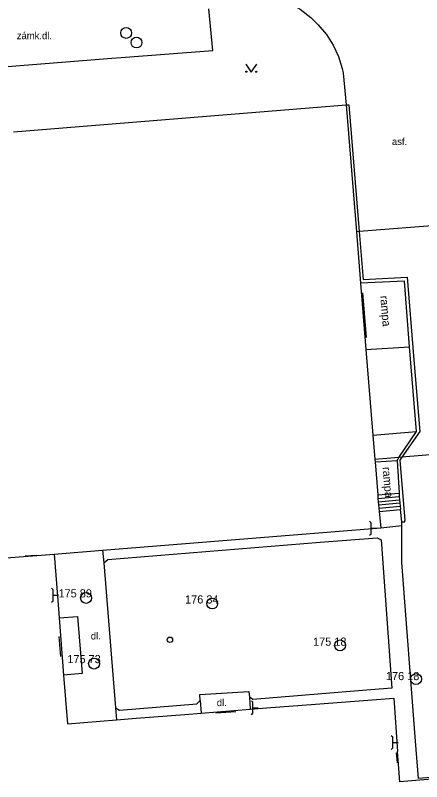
# Model space of a CAD drawing. Extents: x -541281 to -539153, y -1183881 to -1182141.
# Drawn here: x -539516.2 to -539478.9, y -1183295.1 to -1183224.7 of the extents above; entities that cross this region are included whole.
import ezdxf

# ---------------------------------------------------------------- set-up
doc = ezdxf.new("R2010")
doc.units = 0
for name, color, linetype in [('Vrstva 10', 7, 'Continuous'), ('Vrstva 11', 7, 'Continuous'), ('Vrstva 27', 7, 'Continuous'), ('Vrstva 28', 7, 'Continuous'), ('Vrstva 36', 7, 'Continuous'), ('Vrstva 4', 7, 'Continuous'), ('Vrstva 40', 7, 'Continuous'), ('Vrstva 41', 7, 'Continuous'), ('Vrstva 5', 7, 'Continuous'), ('Vrstva 6', 7, 'Continuous')]:
    doc.layers.add(name, color=color, linetype=linetype)

msp = doc.modelspace()

# ---------------------------------------------------------------- linework, layer by layer
at = {"layer": 'Vrstva 10'}
for p, q in [((-539498.11, -1183227.94), (-539498.46, -1183224.11)), ((-539506.51, -1183228.59), (-539498.11, -1183227.94)), ((-539516.96, -1183229.43), (-539507.39, -1183228.66)), ((-539507.39, -1183228.66), (-539506.51, -1183228.59)), ((-539486.15, -1183230.02), (-539485.87, -1183232.95)), ((-539485.87, -1183232.95), (-539485.61, -1183232.94)), ((-539485.61, -1183232.94), (-539484.667, -1183244.582)), ((-539480.51, -1183249.13), (-539484.544, -1183249.32)), ((-539480.05, -1183255.17), (-539480.51, -1183249.13)), ((-539480.27, -1183248.78), (-539479.69, -1183256.01)), ((-539484.05, -1183255.419), (-539480.05, -1183255.17)), ((-539479.39, -1183262.95), (-539480.05, -1183255.17)), ((-539479.69, -1183256.01), (-539479.1, -1183262.96)), ((-539483.412, -1183263.287), (-539479.39, -1183262.95)), ((-539480.94, -1183265.58), (-539480.47, -1183271.14)), ((-539480.74, -1183271.27), (-539480.88, -1183270.12)), ((-539479.5, -1183291.41), (-539480.74, -1183275))]:
    msp.add_line(p, q, dxfattribs=at)
for points in [[(-539492.3, -1183223.07), (-539491.16, -1183223.545), (-539490.09, -1183224.163), (-539489.109, -1183224.914), (-539488.42, -1183225.58)], [(-539488.42, -1183225.58), (-539487.668, -1183226.467), (-539487.045, -1183227.448), (-539486.563, -1183228.506), (-539486.23, -1183229.62), (-539486.15, -1183230.02)], [(-539484.667, -1183244.582), (-539484.31, -1183248.99), (-539480.27, -1183248.78)], [(-539481.19, -1183265.61), (-539481.015, -1183265.352), (-539479.39, -1183262.95)], [(-539479.1, -1183262.96), (-539480.765, -1183265.33), (-539480.94, -1183265.58)], [(-539480.74, -1183275), (-539480.74, -1183271.27), (-539480.46, -1183271.26), (-539480.47, -1183271.14)], [(-539478.08, -1183294.74), (-539479.23, -1183294.84), (-539479.5, -1183291.41)]]:
    msp.add_lwpolyline(points, dxfattribs=at)
at = {"layer": 'Vrstva 11'}
for p, q in [((-539483.212, -1183265.753), (-539481.19, -1183265.61)), ((-539481.19, -1183265.61), (-539481.01, -1183268.61)), ((-539482.966, -1183268.791), (-539481.01, -1183268.61)), ((-539482.941, -1183269.106), (-539480.983, -1183268.924)), ((-539482.916, -1183269.405), (-539480.957, -1183269.223)), ((-539482.892, -1183269.704), (-539480.931, -1183269.523)), ((-539482.868, -1183270.003), (-539480.906, -1183269.821)), ((-539482.844, -1183270.302), (-539480.88, -1183270.12)), ((-539482.67, -1183271.8), (-539480.74, -1183271.602)), ((-539507.73, -1183274.71), (-539488.25, -1183273.13)), ((-539488.25, -1183273.13), (-539483, -1183272.73)), ((-539483, -1183272.73), (-539482.65, -1183272.9)), ((-539482.65, -1183272.9), (-539481.67, -1183286.55)), ((-539508.222, -1183273.869), (-539508.12, -1183275.02)), ((-539508.12, -1183275.02), (-539507.73, -1183274.71)), ((-539508.12, -1183275.02), (-539507.03, -1183288.35)), ((-539512.214, -1183280.081), (-539510.52, -1183279.95)), ((-539510.52, -1183279.95), (-539510.1, -1183285.19)), ((-539510.1, -1183285.19), (-539511.801, -1183285.34)), ((-539481.67, -1183286.55), (-539483.99, -1183286.72)), ((-539494.43, -1183287.58), (-539494.75, -1183287.37)), ((-539494.75, -1183287.37), (-539494.67, -1183288.48)), ((-539483.99, -1183286.72), (-539494.43, -1183287.58)), ((-539506.68, -1183288.56), (-539499.56, -1183287.98)), ((-539499.56, -1183287.98), (-539499.27, -1183287.68)), ((-539499.27, -1183287.68), (-539499.16, -1183288.83)), ((-539507.03, -1183288.35), (-539506.958, -1183289.455)), ((-539507.03, -1183288.35), (-539506.68, -1183288.56))]:
    msp.add_line(p, q, dxfattribs=at)
for points in [[(-539481.01, -1183268.61), (-539480.983, -1183268.924), (-539480.957, -1183269.223), (-539480.931, -1183269.523), (-539480.906, -1183269.821), (-539480.88, -1183270.12)], [(-539499.27, -1183287.68), (-539499.29, -1183287.13), (-539494.81, -1183286.83), (-539494.75, -1183287.37)]]:
    msp.add_lwpolyline(points, dxfattribs=at)
at = {"layer": 'Vrstva 27'}
for p, q in [((-539483.71, -1183271.208), (-539483.568, -1183271.35)), ((-539483.568, -1183272.35), (-539483.568, -1183271.35)), ((-539483.568, -1183271.85), (-539483.08, -1183271.85)), ((-539483.71, -1183272.49), (-539483.568, -1183272.35)), ((-539512.91, -1183277.358), (-539512.768, -1183277.5)), ((-539512.768, -1183278.5), (-539512.768, -1183277.5)), ((-539512.768, -1183278), (-539512.28, -1183278)), ((-539512.91, -1183278.64), (-539512.768, -1183278.5)), ((-539494.56, -1183287.698), (-539494.418, -1183287.84)), ((-539494.418, -1183288.84), (-539494.418, -1183287.84)), ((-539494.418, -1183288.34), (-539493.93, -1183288.34)), ((-539494.56, -1183288.98), (-539494.418, -1183288.84)), ((-539481.72, -1183290.878), (-539481.578, -1183291.02)), ((-539481.578, -1183292.02), (-539481.578, -1183291.02)), ((-539481.578, -1183291.52), (-539481.09, -1183291.52)), ((-539481.72, -1183292.16), (-539481.578, -1183292.02))]:
    msp.add_line(p, q, dxfattribs=at)
for centre in [(-539506.06, -1183226.34), (-539505.11, -1183227.22), (-539509.74, -1183278.25), (-539498.16, -1183278.76), (-539486.42, -1183282.61), (-539509.01, -1183284.28), (-539479.45, -1183285.7)]:
    msp.add_circle(centre, 0.5, dxfattribs=at)
at = {"layer": 'Vrstva 28'}
msp.add_circle((-539502.04, -1183282.09), 0.25, dxfattribs=at)
at = {"layer": 'Vrstva 36'}
msp.add_lwpolyline([(-539495.073, -1183229.201), (-539494.573, -1183229.951), (-539494.073, -1183229.201)], dxfattribs=at)
for centre in [(-539495.023, -1183229.901), (-539494.124, -1183229.901)]:
    msp.add_circle(centre, 0.05, dxfattribs=at)
at = {"layer": 'Vrstva 5'}
for p, q in [((-539516.4, -1183235.41), (-539485.87, -1183232.95)), ((-539534.18, -1183275.9), (-539512.68, -1183274.23)), ((-539512.68, -1183274.23), (-539512.37, -1183278.09)), ((-539493.17, -1183288.36), (-539488.69, -1183288)), ((-539488.69, -1183288), (-539481.48, -1183287.45)), ((-539481.48, -1183287.45), (-539481.14, -1183292.36)), ((-539499.16, -1183288.83), (-539494.67, -1183288.48)), ((-539494.67, -1183288.48), (-539493.17, -1183288.36)), ((-539505.13, -1183289.31), (-539500.66, -1183288.95)), ((-539500.66, -1183288.95), (-539499.16, -1183288.83)), ((-539480.92, -1183295.13), (-539481.06, -1183293.51)), ((-539473.1, -1183294.49), (-539480.92, -1183295.13))]:
    msp.add_line(p, q, dxfattribs=at)
for points in [[(-539485.87, -1183232.95), (-539484.926, -1183244.602), (-539484.544, -1183249.32), (-539484.05, -1183255.419), (-539483.412, -1183263.287), (-539483.229, -1183265.542), (-539483.212, -1183265.753), (-539482.966, -1183268.791), (-539482.941, -1183269.106), (-539482.916, -1183269.405), (-539482.892, -1183269.704), (-539482.868, -1183270.003), (-539482.844, -1183270.302), (-539482.67, -1183271.8)], [(-539476.5, -1183243.96), (-539476.807, -1183243.984), (-539484.667, -1183244.582), (-539484.926, -1183244.602)], [(-539474.83, -1183264.82), (-539475.153, -1183264.848), (-539480.765, -1183265.33), (-539481.015, -1183265.352), (-539483.229, -1183265.542)], [(-539512.68, -1183274.23), (-539508.222, -1183273.869), (-539482.67, -1183271.8)], [(-539512.37, -1183278.09), (-539512.214, -1183280.081), (-539511.801, -1183285.34), (-539511.45, -1183289.81)], [(-539511.45, -1183289.81), (-539506.958, -1183289.455), (-539505.13, -1183289.31)]]:
    msp.add_lwpolyline(points, dxfattribs=at)
at = {"layer": 'Vrstva 6'}
for p, q in [((-539484, -1183254.33), (-539484.34, -1183250.22)), ((-539515.32, -1183274.39), (-539514.29, -1183274.31)), ((-539512.07, -1183283.64), (-539512.21, -1183281.8)), ((-539495.99, -1183288.7), (-539497.83, -1183288.85)), ((-539481.16, -1183293.39), (-539481.23, -1183292.48)), ((-539481.06, -1183293.51), (-539481.14, -1183292.36))]:
    msp.add_line(p, q, dxfattribs=at)

# ---------------------------------------------------------------- texts
at = {"layer": 'Vrstva 4'}
for s, p in [('175 89 ', (-539512.27, -1183278.2)), ('176 34 ', (-539500.65, -1183278.76)), ('175 18 ', (-539488.9, -1183282.64)), ('175 73 ', (-539511.46, -1183284.24)), ('176 18 ', (-539482.21, -1183285.8))]:
    msp.add_text(s, height=0.75, dxfattribs=at).set_placement(p)
at = {"layer": 'Vrstva 40'}
for s, p in [('zámk.dl.', (-539516.103, -1183226.912)), ('asf.', (-539481.657, -1183236.635)), ('dl.', (-539509.303, -1183282.064)), ('dl.', (-539497.74, -1183288.191))]:
    msp.add_text(s, height=0.65, dxfattribs=at).set_placement(p)
at = {"layer": 'Vrstva 41'}
for p in [(-539482.745, -1183250.505), (-539482.529, -1183266.242)]:
    msp.add_text('rampa', height=0.75, rotation=275, dxfattribs=at).set_placement(p)

doc.saveas('drawing.dxf')
